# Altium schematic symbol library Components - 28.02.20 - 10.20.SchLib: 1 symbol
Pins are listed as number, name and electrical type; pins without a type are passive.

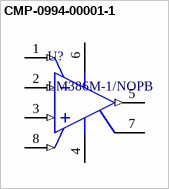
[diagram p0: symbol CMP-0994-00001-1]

## CMP-0994-00001-1
designator U?, comment LM386M-1/NOPB
Low Voltage Audio Power Amplifier, 0 to 70 degC, 8-pin SOIC (D8), Green (RoHS & no Sb/Br); Manufacturer: Texas Instruments; Input Type: Analog; SubFamily: Mid/High-Power Amplifier; Max. Number of Speaker Outputs: 1
footprint TI-D8_N (SOIC, 8-Leads, Body 5x4mm, Pitch 1.27mm, IPC Medium Density)
footprint TI-D8_M (SOIC, 8-Leads, Body 5x4mm, Pitch 1.27mm, IPC Low Density)
footprint TI-D8_L (SOIC, 8-Leads, Body 5x4mm, Pitch 1.27mm, IPC High Density)
pins: 1 GAIN (in), 2 IN- (in), 3 IN+ (in), 4 GND (power), 5 VOUT (out), 6 VS (power), 7 BYPASS, 8 GAIN (in)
